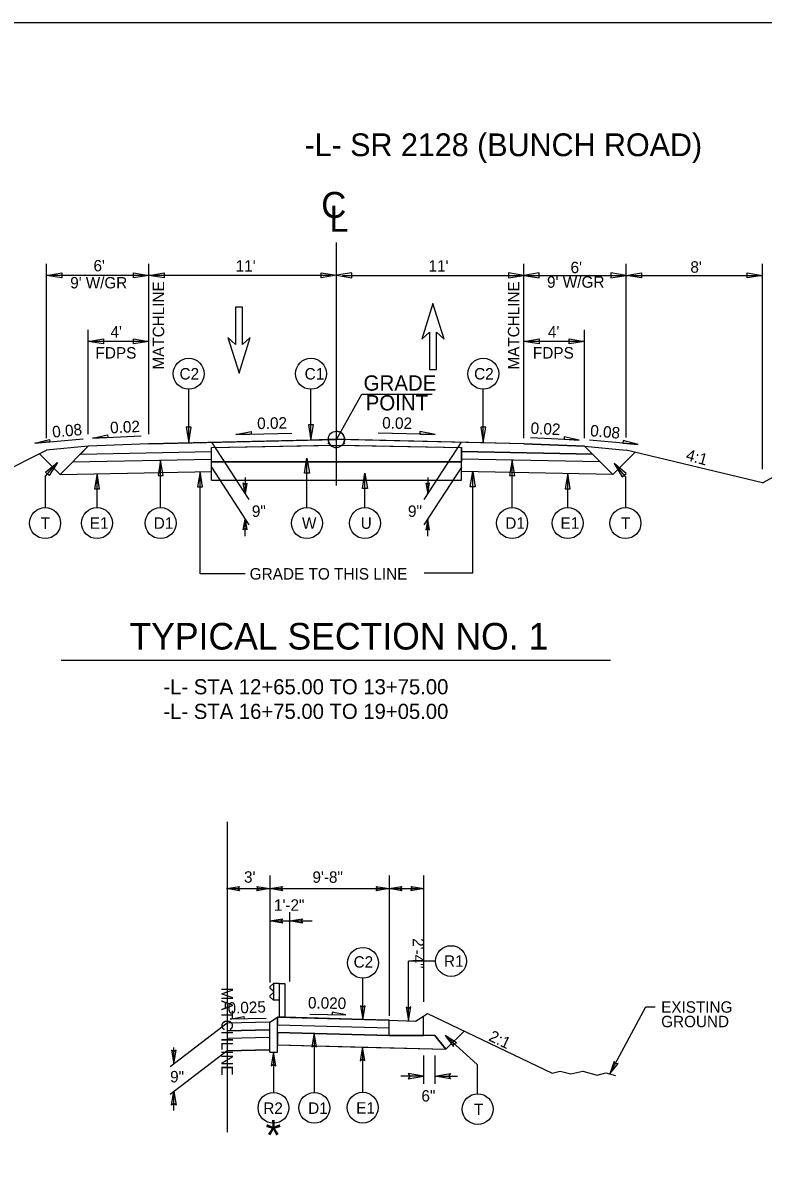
# Model space of a CAD drawing. Extents: x 574442 to 2463611, y -53527 to 675895.
# Drawn here: x 574493.9 to 574537.4, y -53471.4 to -53404.9 of the extents above; entities that cross this region are included whole.
import ezdxf

# ---------------------------------------------------------------- set-up
doc = ezdxf.new("R2010")
doc.units = 0
for name, color, linetype in [('Old_Level_1', 7, 'Continuous'), ('Old_Level_11', 7, 'Continuous'), ('Old_Level_2', 7, 'Continuous'), ('Old_Level_21', 7, 'Continuous'), ('Old_Level_22', 7, 'Continuous'), ('Old_Level_23', 7, 'Continuous'), ('Old_Level_3', 7, 'Continuous'), ('Old_Level_49', 7, 'Continuous'), ('Prop Shade Heavy', 7, 'Continuous'), ('Sheet Plot Border Outside CELL', 7, 'Continuous'), ('Typical Curb CELL', 7, 'Continuous'), ('Typical Guardrail CELL', 7, 'Continuous')]:
    doc.layers.add(name, color=color, linetype=linetype)

msp = doc.modelspace()

# ---------------------------------------------------------------- linework, layer by layer
at = {"layer": 'Old_Level_1'}
msp.add_line((574505.943, -53456.763), (574505.943, -53456.763), dxfattribs=at)
at = {"layer": 'Old_Level_11'}
for p, q in [((574505.037, -53429.511), (574507.219, -53432.866)), ((574519.675, -53429.511), (574517.493, -53432.866)), ((574505.023, -53430.975), (574507.219, -53434.351)), ((574519.69, -53430.975), (574517.493, -53434.351))]:
    msp.add_line(p, q, dxfattribs=at)
for points in [[(574507.105, -53431.9), (574506.997, -53432.525), (574506.886, -53431.896), (574506.997, -53431.976)], [(574507.105, -53431.9), (574506.997, -53432.525), (574506.886, -53431.896), (574506.997, -53431.976)], [(574517.608, -53431.9), (574517.715, -53432.525), (574517.826, -53431.896), (574517.715, -53431.976)], [(574517.608, -53431.9), (574517.715, -53432.525), (574517.826, -53431.896), (574517.715, -53431.976)], [(574506.89, -53434.635), (574506.997, -53434.01), (574507.108, -53434.639), (574506.997, -53434.559)], [(574517.823, -53434.635), (574517.715, -53434.01), (574517.604, -53434.639), (574517.715, -53434.559)]]:
    msp.add_lwpolyline(points, close=True, dxfattribs=at)
for centre in [(574503.69, -53425.49), (574510.864, -53425.49), (574520.974, -53425.49), (574495.268, -53434.251), (574498.311, -53434.247), (574502.042, -53434.247), (574510.628, -53434.247), (574514.031, -53434.247), (574522.667, -53434.247), (574525.927, -53434.247), (574529.314, -53434.251)]:
    msp.add_circle(centre, 0.909, dxfattribs=at)
at = {"layer": 'Old_Level_21'}
for p, q in [((574506.997, -53431.57), (574506.997, -53432.525)), ((574517.715, -53431.57), (574517.715, -53432.525)), ((574506.997, -53435.011), (574506.997, -53434.01)), ((574517.715, -53435.011), (574517.715, -53434.01))]:
    msp.add_line(p, q, dxfattribs=at)
at = {"layer": 'Old_Level_22'}
for p, q in [((574537.356, -53431.886), (574543.753, -53428.391)), ((574501.356, -53429.596), (574512.356, -53429.342)), ((574511.899, -53429.392), (574511.859, -53429.352)), ((574511.899, -53429.392), (574511.859, -53429.352)), ((574512.354, -53429.338), (574511.877, -53429.338)), ((574512.354, -53429.338), (574512.354, -53428.861)), ((574512.832, -53429.338), (574512.354, -53429.338)), ((574512.354, -53429.816), (574512.354, -53429.338)), ((574523.356, -53429.596), (574512.356, -53429.342)), ((574512.814, -53429.392), (574512.854, -53429.352)), ((574512.814, -53429.392), (574512.854, -53429.352)), ((574478.69, -53438.312), (574495.356, -53429.978)), ((574497.801, -53429.738), (574495.356, -53429.978)), ((574497.801, -53429.738), (574496.144, -53431.395)), ((574501.356, -53429.596), (574497.801, -53429.738)), ((574505.025, -53431.724), (574505.025, -53429.82)), ((574511.899, -53429.605), (574511.859, -53429.566)), ((574511.899, -53429.605), (574511.859, -53429.566)), ((574512.814, -53429.605), (574512.854, -53429.566)), ((574512.814, -53429.605), (574512.854, -53429.566)), ((574519.692, -53431.724), (574519.692, -53429.82)), ((574523.356, -53429.596), (574526.912, -53429.738)), ((574526.912, -53429.738), (574528.569, -53431.395)), ((574526.912, -53429.738), (574529.356, -53429.978)), ((574537.356, -53431.886), (574529.356, -53429.978)), ((574496.144, -53431.395), (574494.936, -53430.188)), ((574496.88, -53430.659), (574505.025, -53430.496)), ((574497.34, -53430.199), (574505.025, -53430.045)), ((574505.023, -53430.377), (574505.025, -53430.045)), ((574505.025, -53430.655), (574519.692, -53430.655)), ((574519.69, -53430.377), (574519.692, -53430.045)), ((574527.372, -53430.198), (574519.692, -53430.045)), ((574527.833, -53430.659), (574519.692, -53430.496)), ((574528.569, -53431.395), (574529.865, -53430.1)), ((574496.144, -53431.395), (574505.037, -53431.217)), ((574528.569, -53431.395), (574519.692, -53431.218)), ((574505.025, -53431.724), (574519.692, -53431.724)), ((574505.943, -53451.768), (574505.943, -53469.967)), ((574508.903, -53463.227), (574515.443, -53463.397)), ((574517.466, -53463.179), (574517.705, -53463.016)), ((574517.705, -53463.016), (574525.007, -53466.523)), ((574508.443, -53463.515), (574505.943, -53463.58)), ((574508.903, -53463.678), (574515.443, -53463.848)), ((574508.443, -53463.966), (574505.943, -53464.031)), ((574508.443, -53464.417), (574505.943, -53464.482)), ((574508.443, -53464.417), (574505.943, -53464.482)), ((574505.943, -53464.482), (574505.943, -53465.204)), ((574508.443, -53465.139), (574508.443, -53464.417)), ((574508.903, -53464.129), (574515.443, -53464.299)), ((574515.443, -53464.299), (574508.903, -53464.129)), ((574508.903, -53464.129), (574508.903, -53464.851)), ((574517.466, -53464.299), (574515.443, -53464.299)), ((574518.136, -53464.299), (574517.466, -53464.299)), ((574518.136, -53464.299), (574517.466, -53464.299)), ((574518.136, -53464.299), (574518.784, -53465.108)), ((574518.784, -53465.108), (574518.136, -53464.299)), ((574518.784, -53465.108), (574519.847, -53464.044)), ((574508.443, -53465.139), (574505.943, -53465.204)), ((574505.943, -53465.204), (574508.443, -53465.139)), ((574508.903, -53464.851), (574518.784, -53465.108))]:
    msp.add_line(p, q, dxfattribs=at)
msp.add_lwpolyline([(574505.025, -53429.82), (574512.359, -53429.673), (574519.692, -53429.82), (574519.692, -53430.655), (574505.025, -53430.655)], close=True, dxfattribs=at)
for points in [[(574508.903, -53464.851), (574513.887, -53464.98), (574518.784, -53465.108)], [(574525.007, -53466.523), (574525.476, -53466.395), (574526.114, -53466.555), (574526.807, -53466.395), (574527.646, -53466.623), (574528.156, -53466.486), (574528.74, -53466.646)]]:
    msp.add_lwpolyline(points, dxfattribs=at)
msp.add_circle((574512.354, -53429.338), 0.478, dxfattribs=at)
for start, end in [(180, 270), (0, 90)]:
    msp.add_arc((574512.354, -53429.338), 0.478, start, end, dxfattribs=at)
at = {"layer": 'Old_Level_23'}
for p, q in [((574512.356, -53432.041), (574512.356, -53417.791)), ((574495.356, -53429.259), (574495.356, -53419.046)), ((574501.356, -53429.026), (574501.356, -53419.046)), ((574523.356, -53429.261), (574523.356, -53419.046)), ((574529.356, -53429.221), (574529.356, -53419.046)), ((574537.356, -53431.086), (574537.356, -53419.046)), ((574504.356, -53419.716), (574495.356, -53419.716)), ((574503.023, -53419.716), (574503.023, -53419.716)), ((574512, -53419.716), (574504.356, -53419.716)), ((574512.713, -53419.716), (574520.356, -53419.716)), ((574520.356, -53419.716), (574525.69, -53419.716)), ((574521.69, -53419.716), (574521.69, -53419.716)), ((574525.69, -53419.716), (574537.356, -53419.716)), ((574497.801, -53429.026), (574497.801, -53422.911)), ((574526.912, -53429.261), (574526.912, -53422.911)), ((574499.921, -53423.588), (574497.801, -53423.588)), ((574501.356, -53423.588), (574499.395, -53423.588)), ((574526.912, -53423.588), (574523.356, -53423.588)), ((574503.69, -53429.516), (574503.69, -53426.399)), ((574510.864, -53429.377), (574510.864, -53426.399)), ((574512.358, -53429.338), (574513.84, -53426.68)), ((574513.84, -53426.68), (574517.982, -53426.68)), ((574520.974, -53429.516), (574520.974, -53426.399)), ((574494.653, -53429.566), (574497.506, -53429.31)), ((574498.041, -53429.266), (574500.903, -53429.134)), ((574506.465, -53429.042), (574509.735, -53428.977)), ((574518.144, -53429.042), (574514.811, -53428.976)), ((574526.604, -53429.375), (574523.743, -53429.244)), ((574530.051, -53429.633), (574527.198, -53429.378)), ((574502.042, -53433.338), (574502.042, -53430.555)), ((574510.628, -53433.338), (574510.628, -53430.432)), ((574522.667, -53433.338), (574522.667, -53430.555)), ((574495.268, -53431.521), (574495.988, -53430.692)), ((574498.311, -53433.338), (574498.311, -53431.342)), ((574504.356, -53437.223), (574504.356, -53431.231)), ((574514.031, -53433.338), (574514.031, -53431.321)), ((574520.356, -53437.18), (574520.356, -53431.231)), ((574525.927, -53433.338), (574525.927, -53431.342)), ((574529.314, -53431.521), (574528.651, -53430.759)), ((574495.268, -53431.521), (574495.268, -53433.342)), ((574529.314, -53431.521), (574529.314, -53433.342)), ((574507.012, -53437.223), (574504.356, -53437.223)), ((574520.356, -53437.18), (574517.498, -53437.18)), ((574508.443, -53454.918), (574508.443, -53461.2)), ((574515.443, -53454.918), (574515.443, -53463.15)), ((574517.466, -53454.918), (574517.466, -53462.327)), ((574505.914, -53455.69), (574515.443, -53455.69)), ((574515.443, -53455.69), (574517.488, -53455.69)), ((574509.613, -53457.068), (574509.613, -53461.139)), ((574508.443, -53457.588), (574510.926, -53457.588)), ((574516.581, -53463.432), (574516.581, -53459.94)), ((574518.176, -53459.94), (574516.581, -53459.94)), ((574513.9, -53463.357), (574513.9, -53460.949)), ((574510.801, -53463.045), (574512.911, -53463.085)), ((574528.405, -53466.554), (574530.518, -53462.626)), ((574530.518, -53462.626), (574531.066, -53462.626)), ((574505.943, -53463.578), (574502.598, -53466.138)), ((574508.241, -53463.301), (574506.131, -53463.341)), ((574511.05, -53464.177), (574511.05, -53467.645)), ((574518.729, -53464.3), (574520.608, -53466)), ((574505.943, -53465.204), (574502.598, -53467.764)), ((574502.821, -53465.957), (574502.821, -53465.009)), ((574513.887, -53464.98), (574513.887, -53467.632)), ((574508.674, -53465.281), (574508.674, -53467.632)), ((574517.466, -53465.47), (574517.466, -53467.133)), ((574518.136, -53465.47), (574518.136, -53467.133)), ((574520.608, -53466), (574520.608, -53467.72)), ((574517.466, -53466.685), (574516.134, -53466.685)), ((574518.136, -53466.685), (574519.455, -53466.685)), ((574502.821, -53468.699), (574502.821, -53467.593))]:
    msp.add_line(p, q, dxfattribs=at)
for points in [[(574495.356, -53419.716), (574496.252, -53419.567), (574496.252, -53419.866)], [(574501.356, -53419.716), (574500.461, -53419.866), (574500.461, -53419.567)], [(574501.356, -53419.716), (574502.252, -53419.567), (574502.252, -53419.866)], [(574512.356, -53419.709), (574511.461, -53419.858), (574511.461, -53419.56)], [(574512.356, -53419.709), (574513.252, -53419.858), (574513.252, -53419.56)], [(574523.356, -53419.716), (574522.461, -53419.567), (574522.461, -53419.866)], [(574523.356, -53419.716), (574524.252, -53419.866), (574524.252, -53419.567)], [(574529.356, -53419.716), (574528.461, -53419.567), (574528.461, -53419.866)], [(574529.356, -53419.716), (574530.252, -53419.567), (574530.252, -53419.866)], [(574537.356, -53419.716), (574536.461, -53419.866), (574536.461, -53419.567)], [(574497.801, -53423.588), (574498.696, -53423.439), (574498.696, -53423.737)], [(574501.356, -53423.588), (574500.461, -53423.737), (574500.461, -53423.439)], [(574523.356, -53423.588), (574524.252, -53423.439), (574524.252, -53423.737)], [(574526.912, -53423.588), (574526.016, -53423.737), (574526.016, -53423.439)], [(574503.69, -53429.516), (574503.839, -53428.62), (574503.54, -53428.62)], [(574510.864, -53429.377), (574511.013, -53428.481), (574510.714, -53428.481)], [(574520.974, -53429.516), (574521.123, -53428.62), (574520.825, -53428.62)], [(574494.653, -53429.566), (574495.531, -53429.337), (574495.545, -53429.486)], [(574498.041, -53429.266), (574498.929, -53429.075), (574498.936, -53429.225)], [(574506.465, -53429.042), (574507.357, -53428.875), (574507.36, -53429.024)], [(574518.144, -53429.042), (574517.252, -53428.875), (574517.249, -53429.024)], [(574526.604, -53429.375), (574525.717, -53429.185), (574525.71, -53429.334)], [(574530.051, -53429.633), (574529.173, -53429.405), (574529.159, -53429.553)], [(574502.042, -53430.555), (574501.893, -53431.451), (574502.191, -53431.451)], [(574510.628, -53430.432), (574510.777, -53431.328), (574510.479, -53431.328)], [(574522.667, -53430.555), (574522.518, -53431.451), (574522.816, -53431.451)], [(574495.988, -53430.692), (574495.513, -53431.466), (574495.288, -53431.27)], [(574498.311, -53431.342), (574498.161, -53432.238), (574498.46, -53432.238)], [(574504.356, -53431.231), (574504.207, -53432.127), (574504.506, -53432.127)], [(574514.031, -53431.321), (574514.18, -53432.216), (574513.882, -53432.216)], [(574520.356, -53431.231), (574520.506, -53432.127), (574520.207, -53432.127)], [(574525.927, -53431.342), (574525.778, -53432.238), (574526.076, -53432.238)], [(574528.651, -53430.759), (574529.126, -53431.533), (574529.351, -53431.337)], [(574506.667, -53455.82), (574505.914, -53455.69), (574506.672, -53455.556), (574506.575, -53455.69)], [(574507.689, -53455.56), (574508.443, -53455.69), (574507.685, -53455.824), (574507.781, -53455.69)], [(574509.197, -53455.82), (574508.443, -53455.69), (574509.201, -53455.556), (574509.104, -53455.69)], [(574514.689, -53455.56), (574515.443, -53455.69), (574514.685, -53455.824), (574514.781, -53455.69)], [(574516.197, -53455.82), (574515.443, -53455.69), (574516.201, -53455.556), (574516.104, -53455.69)], [(574516.734, -53455.56), (574517.488, -53455.69), (574516.73, -53455.824), (574516.827, -53455.69)], [(574509.197, -53457.718), (574508.443, -53457.588), (574509.201, -53457.454), (574509.104, -53457.588)], [(574510.367, -53457.718), (574509.613, -53457.588), (574510.371, -53457.454), (574510.274, -53457.588)], [(574513.763, -53462.561), (574513.9, -53463.357), (574514.042, -53462.556), (574513.9, -53462.658)], [(574506.131, -53463.341), (574506.932, -53463.192), (574506.935, -53463.326)], [(574512.911, -53463.085), (574512.11, -53462.935), (574512.107, -53463.069)], [(574516.444, -53462.636), (574516.581, -53463.432), (574516.722, -53462.632), (574516.581, -53462.733)], [(574511.187, -53464.973), (574511.05, -53464.177), (574510.908, -53464.977), (574511.05, -53464.875)], [(574519.411, -53464.732), (574518.729, -53464.3), (574519.227, -53464.942), (574519.247, -53464.769)], [(574502.684, -53465.161), (574502.821, -53465.957), (574502.962, -53465.157), (574502.821, -53465.258)], [(574514.024, -53465.777), (574513.887, -53464.98), (574513.745, -53465.781), (574513.887, -53465.679)], [(574508.811, -53466.077), (574508.674, -53465.281), (574508.532, -53466.081), (574508.674, -53465.979)], [(574528.648, -53465.829), (574528.405, -53466.554), (574528.882, -53465.95), (574528.718, -53465.971)], [(574516.562, -53466.84), (574517.466, -53466.685), (574516.557, -53466.524), (574516.673, -53466.685)], [(574519.041, -53466.84), (574518.136, -53466.685), (574519.046, -53466.524), (574518.93, -53466.685)], [(574502.684, -53468.389), (574502.821, -53467.593), (574502.962, -53468.394), (574502.821, -53468.292)]]:
    msp.add_lwpolyline(points, close=True, dxfattribs=at)
for centre in [(574513.913, -53460.044), (574519.081, -53459.94), (574508.663, -53468.55), (574511.062, -53468.55), (574513.899, -53468.536), (574520.644, -53468.623)]:
    msp.add_circle(centre, 0.904, dxfattribs=at)
at = {"layer": 'Old_Level_3'}
msp.add_line((574496.201, -53442.292), (574528.432, -53442.292), dxfattribs=at)
at = {"layer": 'Old_Level_49'}
for points in [[(574517.369, -53423.46), (574517.816, -53423.047), (574517.816, -53425.247), (574518.229, -53425.247), (574518.229, -53423.047), (574518.676, -53423.46), (574518.023, -53421.363)], [(574507.297, -53423.364), (574506.85, -53423.777), (574506.85, -53421.576), (574506.437, -53421.576), (574506.437, -53423.777), (574505.991, -53423.364), (574506.644, -53425.461)]]:
    msp.add_lwpolyline(points, close=True, dxfattribs=at)
at = {"layer": 'Prop Shade Heavy'}
for p, q in [((574511.877, -53429.371), (574511.861, -53429.354)), ((574512.852, -53429.354), (574512.83, -53429.376)), ((574497.801, -53429.738), (574497.34, -53430.199)), ((574501.356, -53429.596), (574497.801, -53429.738)), ((574505.025, -53429.82), (574512.02, -53429.68)), ((574505.025, -53430.045), (574505.025, -53429.82)), ((574512.687, -53429.68), (574519.692, -53429.82)), ((574519.692, -53429.82), (574519.692, -53430.045)), ((574526.912, -53429.738), (574523.356, -53429.596)), ((574527.372, -53430.198), (574526.912, -53429.738)), ((574497.34, -53430.199), (574505.025, -53430.045)), ((574519.692, -53430.045), (574527.372, -53430.198)), ((574508.903, -53463.227), (574508.903, -53463.678)), ((574508.443, -53463.515), (574505.943, -53463.578)), ((574505.943, -53463.578), (574505.943, -53464.031)), ((574508.443, -53463.966), (574508.443, -53463.515)), ((574508.903, -53463.678), (574515.443, -53463.848)), ((574515.443, -53463.848), (574515.443, -53463.397)), ((574505.943, -53464.031), (574508.443, -53463.966))]:
    msp.add_line(p, q, dxfattribs=at)
for points in [[(574511.861, -53429.354), (574511.859, -53429.354), (574510.864, -53429.377), (574501.356, -53429.596)], [(574523.356, -53429.596), (574512.854, -53429.354), (574512.852, -53429.354)], [(574515.443, -53463.397), (574513.9, -53463.357), (574509.326, -53463.238), (574508.903, -53463.227)]]:
    msp.add_lwpolyline(points, dxfattribs=at)
for start, end in [(183.90273, 225.69804), (314.33446, 355.41837)]:
    msp.add_arc((574512.354, -53429.338), 0.478, start, end, dxfattribs=at)
at = {"layer": 'Sheet Plot Border Outside CELL'}
msp.add_lwpolyline([(574441.833, -53527.117), (574628.889, -53527.117), (574628.889, -53404.895), (574441.833, -53404.895)], close=True, dxfattribs=at)
at = {"layer": 'Typical Curb CELL'}
for p, q in [((574508.443, -53463.515), (574508.903, -53463.227)), ((574508.903, -53465.281), (574508.903, -53463.227)), ((574517.006, -53463.467), (574517.466, -53463.179)), ((574517.466, -53464.299), (574517.466, -53463.179)), ((574508.443, -53465.281), (574508.443, -53463.515)), ((574515.443, -53464.299), (574515.443, -53463.397)), ((574515.443, -53463.397), (574517.006, -53463.467)), ((574515.443, -53464.299), (574517.466, -53464.299)), ((574508.443, -53465.281), (574508.903, -53465.281))]:
    msp.add_line(p, q, dxfattribs=at)
at = {"layer": 'Typical Guardrail CELL'}
for p, q in [((574508.659, -53461.264), (574508.465, -53461.434)), ((574508.992, -53461.264), (574508.659, -53461.264)), ((574508.659, -53461.264), (574508.659, -53462.235)), ((574508.992, -53461.264), (574508.992, -53463.229)), ((574508.992, -53461.264), (574509.326, -53461.264)), ((574509.326, -53461.264), (574509.326, -53463.238)), ((574508.659, -53461.711), (574508.465, -53461.541)), ((574508.659, -53461.789), (574508.465, -53461.959)), ((574508.659, -53461.75), (574508.659, -53461.711)), ((574508.659, -53461.75), (574508.659, -53461.789)), ((574508.659, -53462.235), (574508.465, -53462.065)), ((574508.992, -53462.235), (574508.659, -53462.235))]:
    msp.add_line(p, q, dxfattribs=at)
for centre, major_axis, start_param, end_param in [((574508.495, -53461.487), (0, -0.065), 3.75251, 5.672516), ((574508.495, -53462.012), (0, 0.065), 0.610968, 2.531366)]:
    msp.add_ellipse(centre, major_axis=major_axis, ratio=0.8, start_param=start_param, end_param=end_param, dxfattribs=at)

# ---------------------------------------------------------------- texts
at = {"layer": 'Old_Level_2'}
for s, p in [('GRADE', (574513.951, -53426.481)), ('POINT', (574514.071, -53427.64))]:
    msp.add_text(s, height=0.8978, dxfattribs=at).set_placement(p)
at = {"layer": 'Old_Level_21'}
for s, height, p in [("6'", 0.6667, (574498.106, -53419.482)), ("11'", 0.6733, (574506.444, -53419.503)), ("11'", 0.6733, (574517.759, -53419.503)), ("6'", 0.6733, (574526.091, -53419.589)), ("8'", 0.6733, (574533.124, -53419.563)), ("9' W/GR", 0.6667, (574496.742, -53420.482)), ("9' W/GR", 0.6733, (574524.713, -53420.443)), ("4'", 0.6733, (574499.101, -53423.37)), ("4'", 0.6733, (574524.764, -53423.368)), ('FDPS', 0.6733, (574498.22, -53424.599)), ('FDPS', 0.6733, (574523.884, -53424.597)), ('C2', 0.6733, (574503.152, -53425.827)), ('C1', 0.6733, (574510.492, -53425.827)), ('C2', 0.6733, (574520.436, -53425.827)), ('9"', 0.6733, (574507.394, -53433.886)), ('9"', 0.6733, (574516.553, -53433.886)), ('T', 0.673, (574495.003, -53434.588)), ('E1', 0.6733, (574497.886, -53434.584)), ('D1', 0.6733, (574501.639, -53434.584)), ('W', 0.673, (574510.336, -53434.584)), ('U', 0.673, (574513.779, -53434.584)), ('D1', 0.6733, (574522.264, -53434.584)), ('E1', 0.6733, (574525.503, -53434.584)), ('T', 0.673, (574529.049, -53434.588)), ('GRADE TO THIS LINE', 0.67333, (574507.267, -53437.562)), ('-L- STA 12+65.00 TO 13+75.00', 0.88889, (574502.207, -53444.292)), ('-L- STA 16+75.00 TO 19+05.00', 0.88889, (574502.207, -53445.737))]:
    msp.add_text(s, height=height, dxfattribs=at).set_placement(p)
for s, rotation, p in [('0.02', 1.14576, (574507.713, -53428.736)), ('0.02', 358.85424, (574515.036, -53428.7)), ('0.08', 5.13358, (574495.714, -53429.238)), ('0.02', 2.63199, (574499.094, -53428.985)), ('0.02', 357.36801, (574523.735, -53429.011)), ('0.08', 354.89111, (574527.221, -53429.147)), ('4:1', 344.39866, (574532.816, -53430.539)), ('2:1', 334.3471, (574521.238, -53464.575))]:
    msp.add_text(s, height=0.6733, rotation=rotation, dxfattribs=at).set_placement(p)
at = {"layer": 'Old_Level_23'}
for s, rotation, p in [('MATCHLINE', 90, (574502.249, -53425.243)), ('MATCHLINE', 90, (574523.088, -53425.243)), ("3'", 360, (574506.937, -53455.342)), ('9\'-8"', 360, (574510.951, -53455.349)), ('1\'-2"', 360, (574508.694, -53456.987)), ('2\'-4"', 270, (574516.832, -53458.594)), ('MATCHLINE', 270, (574505.611, -53461.488)), ('0.025', 2, (574505.984, -53463.033)), ('0.020', 358.91555, (574510.682, -53462.713))]:
    msp.add_text(s, height=0.67, rotation=rotation, dxfattribs=at).set_placement(p)
for s, p in [('C2', (574513.366, -53460.324)), ('R1', (574518.669, -53460.275)), ('EXISTING', (574531.409, -53462.969)), ('GROUND', (574531.409, -53463.819)), ('9"', (574502.6, -53467.055)), ('6"', (574517.345, -53468.18)), ('R2', (574508.069, -53468.901)), ('D1', (574510.703, -53468.901)), ('E1', (574513.519, -53468.887)), ('T', (574520.425, -53468.968))]:
    msp.add_text(s, height=0.67, dxfattribs=at).set_placement(p)
at = {"layer": 'Old_Level_3'}
msp.add_text('-L- SR 2128 (BUNCH ROAD)', height=1.33598, rotation=360, dxfattribs=at).set_placement((574510.483, -53412.725))
for s, height, p in [('C', 1.521, (574511.466, -53416.345)), ('L', 1.521, (574511.943, -53417.158)), ('TYPICAL SECTION NO. 1', 1.55993, (574500.212, -53441.665)), ('*', 1.778, (574508.194, -53471.041))]:
    msp.add_text(s, height=height, dxfattribs=at).set_placement(p)

doc.saveas('drawing.dxf')
